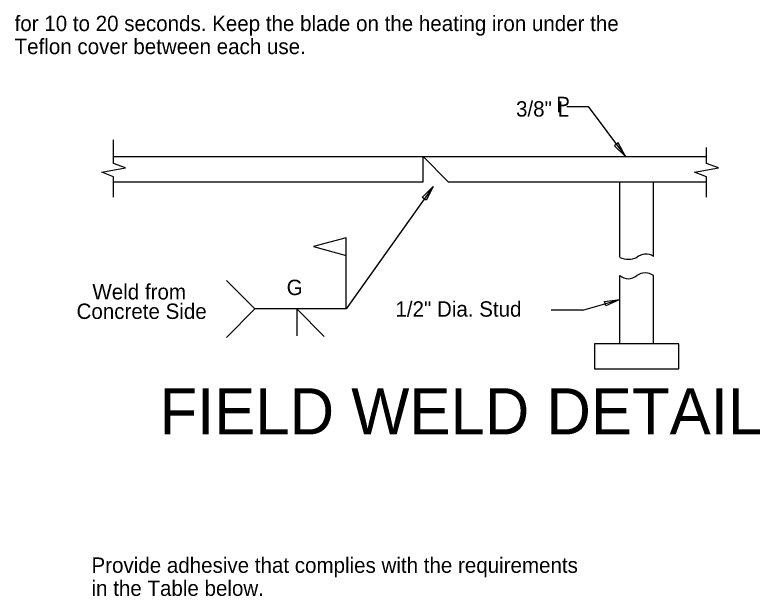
# Model space of a CAD drawing. Extents: x -125.5 to -89.4, y -5.1 to 16.9.
# Drawn here: x -105.09 to -99.03, y 1.06 to 5.79 of the extents above; entities that cross this region are included whole.
import ezdxf

# ---------------------------------------------------------------- set-up
doc = ezdxf.new("R2010")
doc.units = 0
for name, color, linetype in [('BR_AUTO DIMENSION', 7, 'Continuous'), ('BR_STRUCTURAL STEEL', 7, 'Continuous'), ('BR_TABLE LINES', 7, 'Continuous'), ('BR_TEXT', 7, 'Continuous')]:
    doc.layers.add(name, color=color, linetype=linetype)

msp = doc.modelspace()

# ---------------------------------------------------------------- linework, layer by layer
at = {"layer": 'BR_AUTO DIMENSION'}
for p, q in [((-100.6036, 5.0406), (-100.4292, 5.0406)), ((-100.4292, 5.0406), (-100.1256, 4.6319)), ((-101.6916, 4.3894), (-102.3985, 3.3924)), ((-102.3985, 3.3924), (-102.3985, 3.828)), ((-103.1408, 3.3924), (-103.3733, 3.6249)), ((-100.4719, 3.382), (-100.1711, 3.4703)), ((-103.1408, 3.3924), (-103.3733, 3.1599)), ((-102.3985, 3.3924), (-103.1408, 3.3924)), ((-102.801, 3.3924), (-102.801, 3.1733)), ((-102.801, 3.3924), (-102.5779, 3.1693)), ((-100.4719, 3.382), (-100.7301, 3.382))]:
    msp.add_line(p, q, dxfattribs=at)
for points in [[(-100.2152, 4.7211), (-100.1256, 4.6319), (-100.1851, 4.7435)], [(-101.7792, 4.2983), (-101.6916, 4.3894), (-101.7486, 4.2766)], [(-102.3985, 3.828), (-102.3985, 3.9699), (-102.6637, 3.8993)], [(-100.2963, 3.4531), (-100.1711, 3.4703), (-100.2858, 3.4171)]]:
    msp.add_lwpolyline(points, close=True, dxfattribs=at)
at = {"layer": 'BR_STRUCTURAL STEEL'}
for p, q in [((-104.292, 4.6319), (-99.4666, 4.6319)), ((-101.773, 4.4263), (-101.773, 4.6319)), ((-101.5674, 4.4263), (-101.773, 4.6319)), ((-104.292, 4.4263), (-101.773, 4.4263)), ((-101.5674, 4.4263), (-99.4666, 4.4263)), ((-100.1711, 3.8129), (-100.1711, 4.4263)), ((-99.8975, 3.8195), (-99.8975, 4.4263)), ((-100.1711, 3.1084), (-100.1711, 3.664)), ((-99.8975, 3.1084), (-99.8975, 3.664)), ((-99.6919, 3.1084), (-100.3768, 3.1084)), ((-100.3768, 3.1084), (-100.3768, 2.9037)), ((-99.6919, 2.9037), (-99.6919, 3.1084)), ((-100.3768, 2.9037), (-99.6919, 2.9037))]:
    msp.add_line(p, q, dxfattribs=at)
for centre, radius, start, end in [((-99.9598, 3.7189), 0.1192, 58.34056, 128.59806), ((-100.1026, 3.9531), 0.1568, 244.09676, 295.90324), ((-100.1026, 3.7409), 0.103, 228.3227, 311.6773), ((-99.9657, 3.5682), 0.1177, 54.43125, 125.56875)]:
    msp.add_arc(centre, radius, start, end, dxfattribs=at)
at = {"layer": 'BR_TABLE LINES'}
for p, q in [((-104.292, 4.5765), (-104.292, 4.7697)), ((-99.4666, 4.5765), (-99.4666, 4.7069)), ((-104.292, 4.3008), (-104.292, 4.468)), ((-99.4666, 4.3008), (-99.4666, 4.468))]:
    msp.add_line(p, q, dxfattribs=at)
for points in [[(-104.292, 4.468), (-104.3884, 4.5042), (-104.1955, 4.5403), (-104.292, 4.5765)], [(-99.4666, 4.468), (-99.563, 4.5042), (-99.3701, 4.5403), (-99.4666, 4.5765)]]:
    msp.add_lwpolyline(points, dxfattribs=at)
at = {"layer": 'BR_TEXT'}
msp.add_line((-102.3985, 3.9699), (-102.4026, 3.9682), dxfattribs=at)

# ---------------------------------------------------------------- texts
for s, height, p in [('   for 10 to 20 seconds. Keep the blade on the heating iron under the', 0.125, (-105.2362, 5.6537)), ('   Teflon cover between each use.', 0.125, (-105.2362, 5.4662)), ('P', 0.125, (-100.6896, 4.9936)), ('3/8" L', 0.125, (-101.0166, 4.958)), ('Weld from', 0.125, (-104.4639, 3.4695)), (' G ', 0.125, (-102.9293, 3.5051)), ('1/2" Dia. Stud', 0.125, (-101.998, 3.3292)), ('Concrete Side', 0.125, (-104.5928, 3.3108)), ('FIELD WELD DETAIL', 0.375, (-103.9179, 2.3718)), ('Provide adhesive that complies with the requirements', 0.125, (-104.4711, 1.2445)), ('in the Table below.', 0.125, (-104.4711, 1.057))]:
    msp.add_text(s, height=height, dxfattribs=at).set_placement(p)

doc.saveas('drawing.dxf')
